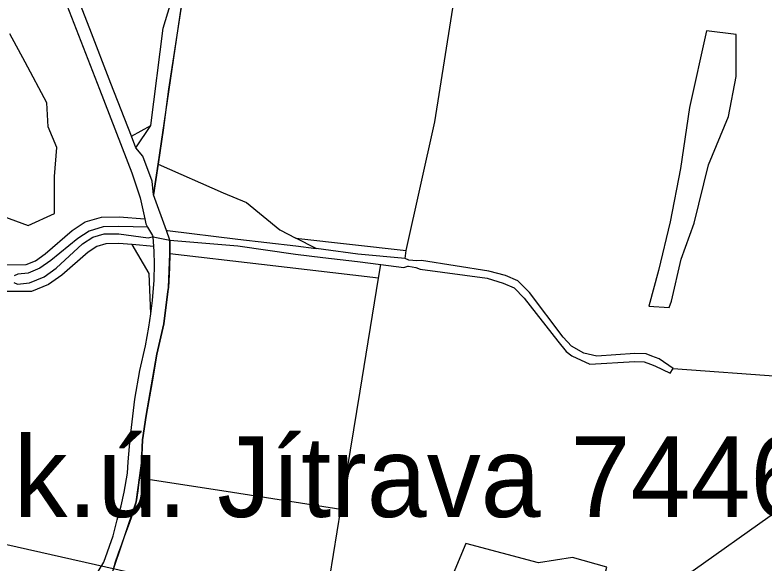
# Model space of a CAD drawing. Extents: x -706771 to -698463, y -971709 to -967107.
# Drawn here: x -702031 to -701472, y -968988 to -968580 of the extents above; entities that cross this region are included whole.
import ezdxf

# ---------------------------------------------------------------- set-up
doc = ezdxf.new("R2010")
doc.units = 0
for name, color, linetype in [('Hranice katastrálních území popis', 7, 'Continuous'), ('KN_Hranice_parcel', 7, 'Continuous'), ('Koridor uzemni rezervy zeleznicni trat - osa N', 7, 'Continuous'), ('Trasy turistické S', 7, 'Continuous')]:
    doc.layers.add(name, color=color, linetype=linetype)

msp = doc.modelspace()

# ---------------------------------------------------------------- linework, layer by layer
at = {"layer": 'KN_Hranice_parcel'}
for p, q in [((-701943.9, -968670.09), (-701929.48, -968662.05)), ((-701940.54, -968678.76), (-701929.48, -968662.05)), ((-701940.54, -968678.76), (-701943.9, -968670.09)), ((-701924.06, -968690.92), (-701927.55, -968713.67)), ((-701917.76, -968740.33), (-701927.55, -968713.67)), ((-701927.18, -968752.03), (-701927.72, -968745.05)), ((-701927.72, -968745.05), (-701915.17, -968747.38)), ((-701915.17, -968747.38), (-701917.76, -968740.33)), ((-701927.18, -968752.03), (-701943.44, -968750.77)), ((-701915.17, -968747.38), (-701915.34, -968757.66)), ((-701821.44, -968745.89), (-701739.38, -968755.06)), ((-701806.23, -968753.63), (-701821.44, -968745.89)), ((-701740.15, -968761.01), (-701739.38, -968755.06)), ((-701759.95, -968775.65), (-701758.3, -968765.52)), ((-701540.52, -968842.97), (-701431.43, -968850.78))]:
    msp.add_line(p, q, dxfattribs=at)
for points in [[(-701929.48, -968662.05), (-701920.12, -968589.62), (-701915.09, -968572.57), (-701914.44, -968568.97), (-701910.58, -968547.61), (-701906.91, -968530.89), (-701901.55, -968509.63), (-701897.88, -968498.62), (-701890.35, -968476.54), (-701887.82, -968469.25), (-701880.77, -968446.62), (-701874.69, -968413.17), (-701871.52, -968406.03), (-701866.57, -968400.48), (-701855.47, -968387.5)], [(-701739.38, -968755.06), (-701718.08, -968659.45), (-701702.07, -968558.85), (-701696.53, -968524.06), (-701689.18, -968480.92), (-701688.95, -968468.23), (-701695.6, -968425.42)], [(-701943.9, -968670.09), (-701959.14, -968630.76), (-701974.89, -968590.12), (-701988.08, -968556.08), (-701993.61, -968542.18), (-702001.09, -968524.33), (-702005.14, -968514.66), (-702017.83, -968484.36), (-702023.17, -968469.34), (-702028.13, -968455.39), (-702031.01, -968447.89)], [(-702034.7, -968465.27), (-702026.73, -968487.68), (-702000.63, -968550), (-701967.64, -968635.12), (-701943.54, -968697.32), (-701937.36, -968716.03), (-701933.97, -968731.44)], [(-701893.3, -968521.57), (-701904.47, -968557.75), (-701916.23, -968634.99), (-701920.18, -968665.59), (-701924.06, -968690.92)], [(-702039.6, -968729.55), (-702020.87, -968736.47), (-702001.03, -968727.54), (-702001.21, -968700.15), (-701999.48, -968678.36), (-702005.9, -968662.97), (-702006.93, -968645.13), (-702023, -968614.89), (-702034.39, -968593.82)], [(-701542.87, -968733.88), (-701551.38, -968769.91), (-701558.57, -968796.56), (-701543.51, -968797.44), (-701541.74, -968792.74), (-701534.56, -968761.57), (-701524.85, -968734.7), (-701514.13, -968691.3), (-701499.21, -968655.33), (-701493.61, -968625.59), (-701493.69, -968594.45), (-701515.72, -968591.69), (-701528.47, -968648.61), (-701535.06, -968694.17), (-701542.87, -968733.88)], [(-701927.55, -968713.67), (-701928.55, -968703.63), (-701935.5, -968684.85), (-701940.54, -968678.76)], [(-701924.06, -968690.92), (-701875.63, -968712.26), (-701858.17, -968719.34), (-701833.32, -968739.85), (-701821.44, -968745.89)], [(-702040.15, -968765.72), (-702022.22, -968765.57), (-702015.37, -968762.76), (-702008.14, -968757.62), (-701988.1, -968740.26), (-701978.23, -968733.84), (-701966.16, -968730.19), (-701952.92, -968729.97), (-701933.97, -968731.44)], [(-701933.97, -968731.44), (-701933.13, -968735.27), (-701931.8, -968737.68)], [(-701931.8, -968737.68), (-701953.21, -968737.16), (-701964.92, -968737.61), (-701975.28, -968740.79), (-701983.76, -968746.27), (-702003.9, -968762.67), (-702012.17, -968768.38), (-702020.75, -968771.88), (-702028.45, -968772.76), (-702031.17, -968773.93)], [(-701931.8, -968737.68), (-701928.3, -968743.99), (-701927.85, -968744.81), (-701927.72, -968745.05)], [(-702031.37, -968778.81), (-702028.74, -968780.2), (-702019.68, -968779.22), (-702008.86, -968774.78), (-702000.01, -968768.29), (-701980.39, -968750.26), (-701972.67, -968745.2), (-701964.29, -968742.72), (-701953.24, -968742.8), (-701931.32, -968745.69), (-701928.47, -968744.95), (-701927.72, -968745.05)], [(-701917.76, -968740.33), (-701917.08, -968740.22), (-701864.58, -968746.57), (-701821.46, -968751.55), (-701806.23, -968753.63)], [(-701943.44, -968750.77), (-701953.53, -968749.99), (-701963.05, -968750.14), (-701969.72, -968752.16), (-701976.05, -968756.27), (-701995.76, -968773.36), (-702005.66, -968780.4), (-702018.21, -968785.53), (-702037.92, -968785.7)], [(-701929.48, -968802.22), (-701930.78, -968772.18), (-701943.44, -968750.77)], [(-701915.17, -968747.38), (-701864.71, -968751.66), (-701821.69, -968757.74), (-701801.26, -968760.24), (-701775.45, -968763.39), (-701758.3, -968765.52)], [(-701929.48, -968802.22), (-701928.08, -968792.22), (-701926.85, -968777.22), (-701926.57, -968765.27), (-701926.88, -968755.95), (-701927.18, -968752.03)], [(-701740.15, -968761.01), (-701775.26, -968757.85), (-701800.88, -968754.36), (-701806.23, -968753.63)], [(-701915.34, -968757.66), (-701915.52, -968767.95), (-701916.27, -968782.54), (-701916.67, -968785.72), (-701919.71, -968809.62), (-701924.9, -968832.32), (-701928.41, -968852.79), (-701933.02, -968877.91), (-701935.66, -968896.04), (-701936.48, -968913.52), (-701937.91, -968924.22)], [(-701759.95, -968775.65), (-701847.13, -968765.56), (-701915.34, -968757.66)], [(-701540.52, -968842.97), (-701550.95, -968835.82), (-701556.46, -968833.68), (-701560.66, -968832.05), (-701569.06, -968831.75), (-701597.31, -968833.88), (-701607.16, -968831.46), (-701616.32, -968826.31), (-701622.31, -968819.56), (-701647.39, -968786.46), (-701656.14, -968777.81), (-701665.3, -968773.6), (-701677.67, -968770.58), (-701727.95, -968762.67), (-701731.42, -968762.88), (-701737.42, -968762.21), (-701740.15, -968761.01)], [(-701758.3, -968765.52), (-701741.15, -968767.65), (-701738.05, -968766.75), (-701737.56, -968766.82), (-701732.11, -968767.75), (-701728.94, -968769.04), (-701679.13, -968775.74), (-701667.18, -968779.33), (-701659, -968782.79), (-701651.51, -968790.63), (-701626.41, -968822.68), (-701620.21, -968830.23), (-701615.89, -968833.55), (-701602.57, -968839.69), (-701569.01, -968837.71), (-701562.08, -968838.1), (-701557.41, -968839.83), (-701554.13, -968841.04), (-701542.77, -968846.33), (-701540.52, -968842.97)], [(-701787.95, -968947.73), (-701773.63, -968859.73), (-701759.95, -968775.65)], [(-701933.57, -969101.89), (-701954.53, -969052.52), (-701960.51, -969038.62), (-701969.5, -969024.78), (-701976.85, -969012.29), (-701975.46, -969005.57), (-701964.42, -968987.16), (-701957.55, -968967.41), (-701954.56, -968955.49), (-701951.51, -968945.28), (-701949.16, -968935.07), (-701946.73, -968920.8), (-701946.38, -968912.49), (-701944.92, -968895.25), (-701941.37, -968865.79), (-701937.68, -968844.41), (-701933.34, -968826.14), (-701930.88, -968812.23), (-701929.48, -968802.22)], [(-701937.91, -968924.22), (-701938.35, -968927.46), (-701939.09, -968933.93), (-701940.42, -968942.26), (-701942.72, -968950.73), (-701946.2, -968960.35), (-701949.09, -968967.46), (-701951.36, -968973.99), (-701953.64, -968980.52), (-701955.94, -968987.11), (-701958.48, -968995.93), (-701958.9, -969006.68), (-701960.15, -969013.95), (-701957.8, -969024.53), (-701953.12, -969039.66), (-701939.02, -969074.81), (-701937.18, -969078.31), (-701931.9, -969086.98), (-701924.7, -969093.31), (-701911.66, -969097.17), (-701886.97, -969103.3), (-701878.62, -969105.54)], [(-701937.91, -968924.22), (-701868.61, -968935.08), (-701787.95, -968947.73)], [(-701864.64, -969107.96), (-701831.27, -969054.52), (-701796.18, -968998.33), (-701787.95, -968947.73)], [(-701642.18, -969150.25), (-701625.2, -969106.09), (-701610.67, -969068.29), (-701600.4, -969029.83), (-701590.01, -968990.93), (-701615.53, -968983.6), (-701640.8, -968987.68), (-701694.85, -968973.2), (-701709.39, -969007.74), (-701725.27, -969045.48), (-701727, -969048.87)]]:
    msp.add_lwpolyline(points, dxfattribs=at)
at = {"layer": 'Koridor uzemni rezervy zeleznicni trat - osa N'}
msp.add_lwpolyline([(-700670.52, -968515.75), (-700893.06, -968571.74), (-701041.03, -968647.57), (-701166.81, -968728.96), (-701324.03, -968845.48), (-701410.96, -968912.07), (-701525.64, -968993.45), (-701577.43, -969015.65), (-701644.01, -969034.15), (-701718, -969037.85), (-701836.38, -969019.35), (-702247, -968926.87), (-702439.36, -968886.18), (-702574.39, -968862.13), (-702702.01, -968849.18), (-702786.02, -968846.95), (-702842.65, -968850.23), (-702879.77, -968855.14), (-702924.39, -968864.25), (-702967.67, -968876.1), (-703020.15, -968893.57), (-703051.52, -968908.94), (-703080.69, -968927.25)], dxfattribs=at)
at = {"layer": 'Trasy turistické S'}
msp.add_lwpolyline([(-701958.48, -968995.93), (-701940.42, -968942.26), (-701940.42, -968942.26), (-701937.91, -968924.22), (-701936.48, -968913.52), (-701935.66, -968896.04), (-701933.02, -968877.91), (-701924.9, -968832.32), (-701919.71, -968809.62), (-701916.67, -968785.72), (-701916.27, -968782.54), (-701915.34, -968757.66), (-701915.17, -968747.38), (-701917.76, -968740.33), (-701927.55, -968713.67), (-701924.06, -968690.92), (-701904.47, -968557.75)], dxfattribs=at)

# ---------------------------------------------------------------- texts
at = {"layer": 'Hranice katastrálních území popis'}
msp.add_text('k.ú. Jítrava 744689', height=60, dxfattribs=at).set_placement((-702031.61, -968953.48))

doc.saveas('drawing.dxf')
